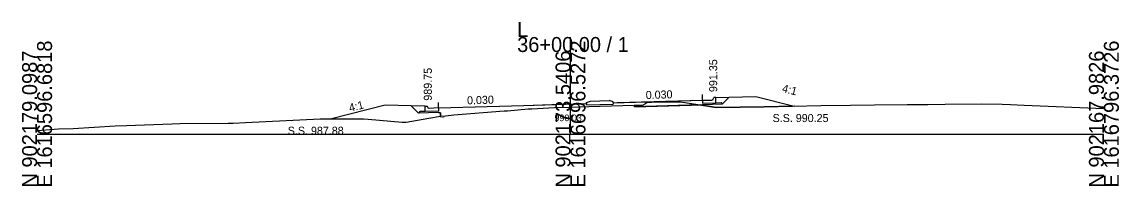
# Model space of a CAD drawing. Extents: x 1009 to 7438, y -1586 to 7964.
# Drawn here: x 3032.1 to 3237.7, y 3914 to 3944.7 of the extents above; entities that cross this region are included whole.
import ezdxf

# ---------------------------------------------------------------- set-up
doc = ezdxf.new("R2010")
doc.units = 0
for name, color, linetype in [('Exist Cross Section Cell', 7, 'Continuous'), ('Exist XS Center Line Elevation Label', 7, 'Continuous'), ('Exist XS Ground Line', 7, 'Continuous'), ('Prop XS Dump Level', 7, 'Continuous'), ('Prop XS Earthwork Shape', 7, 'Continuous'), ('Prop XS EOT Tick Mark', 7, 'Continuous'), ('Prop XS Finish Grade', 7, 'Continuous'), ('Prop XS Finish Grade CurbGutter', 7, 'Continuous'), ('Prop XS Finish Grade Earthwork', 7, 'Continuous'), ('Prop XS Finish Grade Pavement', 7, 'Continuous'), ('Prop XS Hydro Elevations', 7, 'Continuous'), ('Prop XS Pvmt Edge Slope', 7, 'Continuous'), ('Prop XS SE Text', 7, 'Continuous'), ('Prop XS Side Slope Text', 7, 'Continuous'), ('Prop XS SS Elevation Text', 7, 'Continuous'), ('Prop XS Subgrade CurbGutter', 7, 'Continuous'), ('Prop XS Subgrade Earthwork', 7, 'Continuous')]:
    doc.layers.add(name, color=color, linetype=linetype)

msp = doc.modelspace()

# ---------------------------------------------------------------- linework, layer by layer
at = {"layer": 'Exist Cross Section Cell'}
for p, q in [((3134.89, 3923.73), (3134.89, 3941.87)), ((3034.89, 3923.73), (3134.89, 3923.73)), ((3134.89, 3923.73), (3234.89, 3923.73))]:
    msp.add_line(p, q, dxfattribs=at)
at = {"layer": 'Exist XS Ground Line'}
for p, q in [((3127.62, 3928.47), (3131.88, 3928.67)), ((3131.88, 3928.67), (3134.89, 3928.76)), ((3134.89, 3928.76), (3138.35, 3928.87)), ((3138.35, 3928.87), (3146.83, 3929.12)), ((3146.83, 3929.12), (3148.46, 3929.13)), ((3148.46, 3929.13), (3149.19, 3929.65)), ((3149.19, 3929.65), (3150.08, 3929.67)), ((3150.08, 3929.67), (3154.06, 3929.78)), ((3154.06, 3929.78), (3154.52, 3929.76)), ((3154.52, 3929.76), (3155.51, 3929.77)), ((3155.51, 3929.77), (3156.33, 3929.64)), ((3156.33, 3929.64), (3162.22, 3928.67)), ((3162.22, 3928.67), (3171.23, 3928.82)), ((3171.23, 3928.82), (3181.85, 3929.05)), ((3181.85, 3929.05), (3187.41, 3929.12)), ((3187.41, 3929.12), (3191.87, 3929.19)), ((3191.87, 3929.19), (3198.02, 3929.24)), ((3198.02, 3929.24), (3201.89, 3929.26)), ((3201.89, 3929.26), (3205.16, 3929.33)), ((3205.16, 3929.33), (3211.9, 3929.4)), ((3211.9, 3929.4), (3215.81, 3929.34)), ((3215.81, 3929.34), (3217.39, 3929.26)), ((3217.39, 3929.26), (3219.95, 3929.15)), ((3219.95, 3929.15), (3234.89, 3928.49)), ((3073.95, 3925.88), (3087.95, 3926.61)), ((3087.95, 3926.61), (3090.09, 3926.61)), ((3090.09, 3926.61), (3092.76, 3926.61)), ((3092.76, 3926.61), (3095.66, 3926.61)), ((3095.66, 3926.61), (3096.1, 3926.61)), ((3096.1, 3926.61), (3096.94, 3926.54)), ((3096.94, 3926.54), (3103.32, 3925.96)), ((3104.07, 3925.96), (3108.32, 3926.7)), ((3108.32, 3926.7), (3110.52, 3927.06)), ((3110.52, 3927.06), (3111.45, 3927.17)), ((3111.45, 3927.17), (3113.03, 3927.3)), ((3113.03, 3927.3), (3122.43, 3928.05)), ((3122.43, 3928.05), (3123.07, 3928.1)), ((3123.07, 3928.1), (3126.94, 3928.44)), ((3126.94, 3928.44), (3127.62, 3928.47)), ((3034.89, 3924.4), (3038.92, 3924.7)), ((3038.92, 3924.7), (3041.63, 3924.75)), ((3041.63, 3924.75), (3049.53, 3925.28)), ((3049.53, 3925.28), (3051.65, 3925.35)), ((3051.65, 3925.35), (3060.14, 3925.64)), ((3060.14, 3925.64), (3061.66, 3925.73)), ((3061.66, 3925.73), (3070.74, 3925.76)), ((3070.74, 3925.76), (3071.68, 3925.76)), ((3071.68, 3925.76), (3073.95, 3925.88)), ((3103.32, 3925.96), (3104.07, 3925.96))]:
    msp.add_line(p, q, dxfattribs=at)
at = {"layer": 'Prop XS Dump Level'}
for p, q in [((3110.14, 3928.61), (3126.14, 3929.09)), ((3110.14, 3928.61), (3126.14, 3929.09)), ((3126.14, 3929.09), (3134.89, 3929.36)), ((3126.14, 3929.09), (3134.89, 3929.36)), ((3143.64, 3929.62), (3159.64, 3930.1)), ((3143.64, 3929.62), (3159.64, 3930.1))]:
    msp.add_line(p, q, dxfattribs=at)
at = {"layer": 'Prop XS Earthwork Shape'}
for points in [[(3159.17, 3929.17), (3159.64, 3929.18), (3159.64, 3929.27), (3163.39, 3929.38), (3164.64, 3930.63), (3169.64, 3930.74), (3176.84, 3928.94), (3171.23, 3928.82), (3162.22, 3928.67)], [(3096.94, 3926.54), (3103.32, 3925.96), (3104.07, 3925.96), (3108.32, 3926.7), (3110.52, 3927.06), (3110.52, 3927.71), (3110.14, 3927.7), (3110.14, 3927.78), (3106.39, 3927.67), (3105.04, 3929.03), (3100.14, 3929.13), (3090.07, 3926.61), (3090.09, 3926.61), (3092.76, 3926.61), (3095.66, 3926.61), (3096.1, 3926.61)], [(3148.46, 3929.13), (3149.19, 3929.65), (3150.08, 3929.67), (3154.06, 3929.78), (3154.52, 3929.76), (3155.51, 3929.77), (3156.33, 3929.64), (3159.17, 3929.17), (3146.87, 3928.8), (3146.87, 3929.12)]]:
    msp.add_lwpolyline(points, close=True, dxfattribs=at)
at = {"layer": 'Prop XS EOT Tick Mark'}
for p, q in [((3159.64, 3930.1), (3159.64, 3931.1)), ((3110.14, 3928.61), (3110.14, 3929.61))]:
    msp.add_line(p, q, dxfattribs=at)
at = {"layer": 'Prop XS Finish Grade'}
for p, q in [((3162.14, 3930.58), (3164.64, 3930.63)), ((3107.64, 3928.97), (3105.04, 3929.03))]:
    msp.add_line(p, q, dxfattribs=at)
at = {"layer": 'Prop XS Finish Grade CurbGutter'}
for p, q in [((3161.89, 3930.58), (3161.77, 3930.54)), ((3162.14, 3930.58), (3161.89, 3930.58)), ((3107.64, 3928.97), (3107.89, 3928.97)), ((3107.89, 3928.97), (3108.02, 3928.95)), ((3108.11, 3928.86), (3108.02, 3928.95)), ((3108.18, 3928.61), (3108.11, 3928.86)), ((3108.27, 3928.52), (3108.18, 3928.61)), ((3110.14, 3928.61), (3108.39, 3928.49)), ((3137.89, 3929.62), (3138.64, 3929.87)), ((3137.89, 3929.45), (3137.89, 3929.62)), ((3138.64, 3929.87), (3142.14, 3930.02)), ((3142.89, 3929.77), (3142.14, 3930.02)), ((3142.89, 3929.6), (3142.89, 3929.77)), ((3159.64, 3930.1), (3161.39, 3930.08)), ((3161.39, 3930.08), (3161.52, 3930.11)), ((3161.52, 3930.11), (3161.61, 3930.2)), ((3161.61, 3930.2), (3161.68, 3930.45)), ((3161.68, 3930.45), (3161.77, 3930.54)), ((3108.39, 3928.49), (3108.27, 3928.52))]:
    msp.add_line(p, q, dxfattribs=at)
at = {"layer": 'Prop XS Finish Grade Earthwork'}
for p, q in [((3164.64, 3930.63), (3169.64, 3930.74)), ((3169.64, 3930.74), (3176.84, 3928.94)), ((3100.14, 3929.13), (3090.07, 3926.61)), ((3105.04, 3929.03), (3100.14, 3929.13))]:
    msp.add_line(p, q, dxfattribs=at)
at = {"layer": 'Prop XS Finish Grade Pavement'}
for p, q in [((3110.14, 3928.61), (3126.14, 3929.09)), ((3126.14, 3929.09), (3137.89, 3929.45)), ((3142.89, 3929.6), (3159.64, 3930.1))]:
    msp.add_line(p, q, dxfattribs=at)
at = {"layer": 'Prop XS Pvmt Edge Slope'}
for p, q in [((3162.14, 3929.59), (3163.14, 3929.62)), ((3163.14, 3929.62), (3163.39, 3929.38)), ((3106.64, 3927.93), (3106.39, 3927.67)), ((3107.64, 3927.96), (3106.64, 3927.93))]:
    msp.add_line(p, q, dxfattribs=at)
at = {"layer": 'Prop XS Subgrade CurbGutter'}
for p, q in [((3162.14, 3929.59), (3162.14, 3930.58)), ((3107.64, 3927.96), (3107.64, 3928.97)), ((3110.14, 3928.61), (3110.14, 3928.03)), ((3137.89, 3929.45), (3137.89, 3929.2)), ((3137.89, 3929.2), (3142.89, 3929.35)), ((3142.89, 3929.6), (3142.89, 3929.35)), ((3159.64, 3930.1), (3159.64, 3929.52)), ((3159.64, 3929.52), (3162.14, 3929.59)), ((3110.14, 3928.03), (3107.64, 3927.96))]:
    msp.add_line(p, q, dxfattribs=at)
at = {"layer": 'Prop XS Subgrade Earthwork'}
for p, q in [((3163.39, 3929.38), (3164.64, 3930.63)), ((3106.39, 3927.67), (3105.04, 3929.03)), ((3146.87, 3928.8), (3159.64, 3929.18)), ((3146.87, 3928.8), (3146.87, 3929.12)), ((3146.87, 3928.8), (3146.87, 3929.12)), ((3159.64, 3929.27), (3163.39, 3929.38)), ((3159.64, 3929.18), (3159.64, 3929.27)), ((3110.14, 3927.78), (3106.39, 3927.67)), ((3110.14, 3927.7), (3110.14, 3927.78)), ((3110.52, 3927.71), (3110.14, 3927.7)), ((3110.52, 3927.71), (3110.52, 3927.06))]:
    msp.add_line(p, q, dxfattribs=at)

# ---------------------------------------------------------------- texts
at = {"layer": 'Exist Cross Section Cell'}
for s, p in [('L', (3124.89, 3941.87)), ('36+00.00 / 1', (3124.89, 3939.07))]:
    msp.add_text(s, height=2.8, dxfattribs=at).set_placement(p)
for s, p in [('E 1616596.6818', (3037.69, 3913.73)), ('E 1616696.5272', (3137.69, 3913.73)), ('E 1616796.3726', (3237.69, 3913.73)), ('N 902179.0987', (3034.89, 3913.73)), ('N 902173.5406', (3134.89, 3913.73)), ('N 902167.9826', (3234.89, 3913.73))]:
    msp.add_text(s, height=2.8, rotation=90, dxfattribs=at).set_placement(p)
at = {"layer": 'Exist XS Center Line Elevation Label'}
msp.add_text('990.03', height=1.25, dxfattribs=at).set_placement((3131.89, 3926.14))
at = {"layer": 'Prop XS Dump Level'}
for p in [(3146.87, 3928.82), (3146.87, 3928.82), (3146.87, 3928.82), (3110.52, 3926.76)]:
    msp.add_text('Eop', height=0.3, dxfattribs=at).set_placement(p)
at = {"layer": 'Prop XS Hydro Elevations'}
for s, p in [('991.35', (3162.39, 3931.58)), ('989.75', (3108.89, 3929.97))]:
    msp.add_text(s, height=1.5, rotation=90, dxfattribs=at).set_placement(p)
at = {"layer": 'Prop XS SE Text'}
for p in [(3115.52, 3929.28), (3149.02, 3930.28)]:
    msp.add_text('0.030', height=1.5, rotation=1.7184, dxfattribs=at).set_placement(p)
at = {"layer": 'Prop XS Side Slope Text'}
for rotation, p in [(345.9638, (3174.45, 3931.62)), (14.0362, (3093.55, 3927.87))]:
    msp.add_text('4:1', height=1.5, rotation=rotation, dxfattribs=at).set_placement(p)
at = {"layer": 'Prop XS SS Elevation Text'}
for s, p in [('S.S. 990.25', (3172.78, 3925.98)), ('S.S. 987.88', (3081.89, 3923.61))]:
    msp.add_text(s, height=1.5, dxfattribs=at).set_placement(p)

doc.saveas('drawing.dxf')
